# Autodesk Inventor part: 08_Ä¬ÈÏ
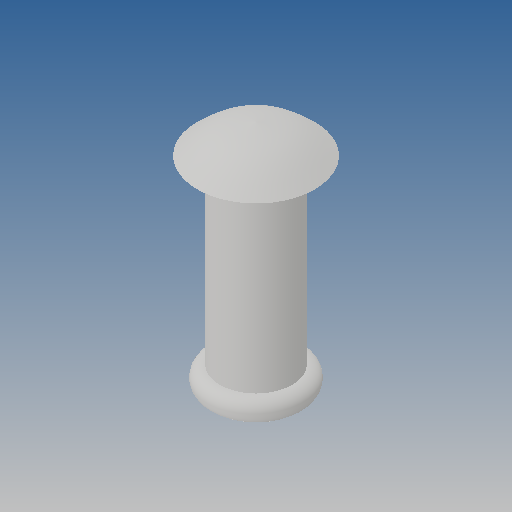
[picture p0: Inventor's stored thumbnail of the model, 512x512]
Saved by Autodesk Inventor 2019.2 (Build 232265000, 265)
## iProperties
Created: 2010-06
Part Number: 08_Ä¬ÈÏ
Material: Ogólny
Document SubType Name: Modeling
Designer: CADENGINEERING4
Density: 1 g/cm^3
Appearance: Domyślna
Author: CADENGINEERING4
Revision Number: ÈÎºÎ
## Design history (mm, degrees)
feature "NONE"
node "Bryła1"
